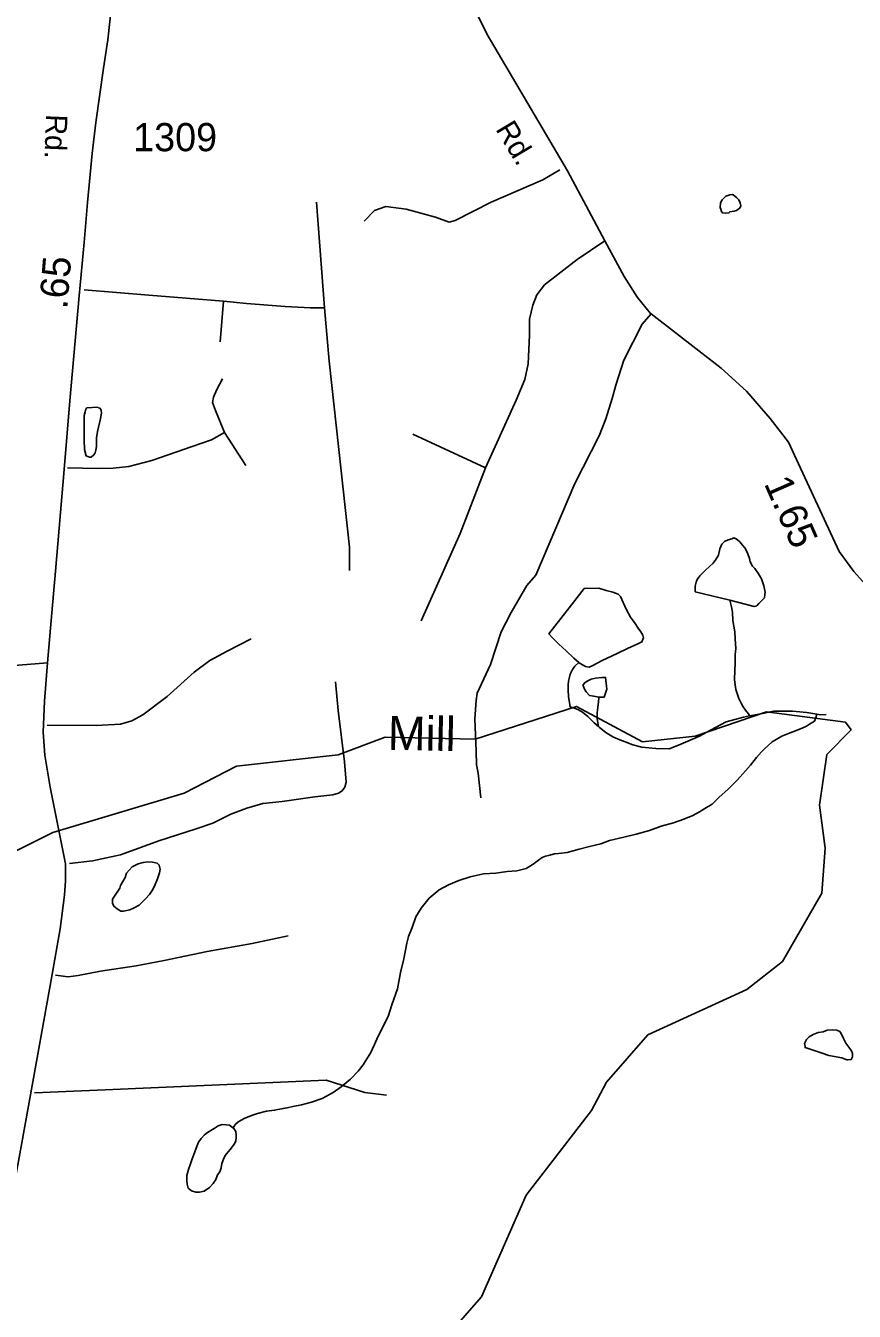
# Model space of a CAD drawing. Extents: x 2082433 to 2279600, y 546599 to 755198.
# Drawn here: x 2116350 to 2120022, y 621201 to 626902 of the extents above; entities that cross this region are included whole.
import ezdxf

# ---------------------------------------------------------------- set-up
doc = ezdxf.new("R2010")
doc.units = 0
for name, color, linetype in [('Exist Hydrographic Creek Single Shore', 7, 'Continuous'), ('Exist Hydrographic Creek Single Shore Label', 7, 'Continuous'), ('Exist Hydrographic Misc Water Feature', 7, 'Continuous'), ('Exist Road Non-System Type 51', 7, 'Continuous'), ('Exist Road Secondary Mileage Hundredths English Label', 7, 'Continuous'), ('Exist Road Secondary Type 51 Attributed', 7, 'Continuous'), ('Exist Road Secondary Type 51 Label', 7, 'Continuous'), ('Exist Road Secondary Type 51 Number Label', 7, 'Continuous')]:
    doc.layers.add(name, color=color, linetype=linetype)

msp = doc.modelspace()

# ---------------------------------------------------------------- linework, layer by layer
at = {"layer": 'Exist Hydrographic Creek Single Shore'}
for points in [[(2115933.5, 622147), (2115831.6, 622486.9), (2115839.6, 622696.8), (2115905.4, 622869.3), (2116162.6, 623172.4), (2116469.5, 623323.7), (2117052.5, 623498.9), (2117284.6, 623618.9), (2117734.5, 623668.8), (2117942.7, 623746.6), (2118342.5, 623738.5), (2118791.6, 623883.5), (2119083.6, 623726.7), (2119317.5, 623751.5), (2119633.7, 623860), (2119983.6, 623813.4), (2120008.6, 623780.1)], [(2117254.4, 619226.7), (2117410.5, 619676.3), (2117433.5, 620161.4), (2117506.5, 620461.7), (2117680.6, 620704.2), (2118129.6, 620990.4), (2118369.6, 621264.4), (2118567.6, 621716.3), (2118857.6, 622091), (2118923.6, 622217.6), (2119106.5, 622427.1), (2119546.6, 622628.1), (2119704.7, 622752.9), (2119878.6, 623054.5), (2119893.5, 623254.3), (2119868.7, 623445), (2119900.7, 623670.7), (2120008.6, 623780.1)]]:
    msp.add_lwpolyline(points, dxfattribs=at)
at = {"layer": 'Exist Hydrographic Misc Water Feature'}
for points in [[(2119470.6, 626076), (2119490.5, 626080.3), (2119500.6, 626082.4), (2119506.3, 626086.4), (2119514.5, 626092.4), (2119520, 626102.5), (2119516.3, 626116.5), (2119510.2, 626130.4), (2119500.4, 626140.4), (2119485.8, 626152.3), (2119481.9, 626154.2), (2119470.2, 626152.3), (2119452.2, 626146.1), (2119436.2, 626129.9), (2119430, 626116.2), (2119428.4, 626096.1), (2119430.4, 626088.1), (2119434.3, 626078.2), (2119438.4, 626071.9), (2119452.6, 626070.2), (2119466.5, 626072.1), (2119470.6, 626076)], [(2116620.8, 625207.9), (2116668.8, 625210.3), (2116672.7, 625208.1), (2116679.2, 625206.3), (2116684.8, 625196.2), (2116685.4, 625184.3), (2116679.2, 625152.4), (2116671.7, 625122.3), (2116667.4, 625102.3), (2116663.7, 625074.1), (2116663.7, 625048.5), (2116663.7, 625036.3), (2116660.2, 625020.2), (2116657.7, 625008.4), (2116651.8, 624998.3), (2116639.9, 624988), (2116631.9, 624988), (2116617.9, 624994.1), (2116609.9, 625022.1), (2116609.5, 625066), (2116609.5, 625113.8), (2116608.9, 625152), (2116609.3, 625173.9), (2116613.2, 625190), (2116616.9, 625202), (2116620.8, 625207.9)], [(2119470.2, 624354.4), (2119578.3, 624327.1), (2119590.2, 624329.4), (2119599.8, 624339.3), (2119623.8, 624365.2), (2119625.6, 624379.2), (2119627.7, 624389.4), (2119621.7, 624417.5), (2119611.5, 624449.5), (2119597.5, 624471), (2119581.1, 624495), (2119571.3, 624505), (2119561, 624525.2), (2119557.2, 624539.2), (2119546.9, 624567.1), (2119536.9, 624586.9), (2119526.6, 624599), (2119514.5, 624612.9), (2119504.7, 624622.6), (2119498.5, 624626.7), (2119488.7, 624630.7), (2119479, 624626.4), (2119463, 624622.4), (2119446.8, 624614.7), (2119434.9, 624602.3), (2119426.9, 624582.4), (2119421, 624554.5), (2119409.1, 624534.4), (2119397.2, 624518.4), (2119381.2, 624504.2), (2119361.5, 624486), (2119337.5, 624462.1), (2119325.6, 624446.1), (2119322, 624434), (2119317.7, 624416), (2119317.7, 624396.2), (2119317.4, 624392.2), (2119470.2, 624354.4)], [(2118801.3, 624077.7), (2118779.2, 624097.6), (2118744.9, 624129.6), (2118713, 624159.6), (2118684.9, 624187.4), (2118668.7, 624205.2), (2118748.2, 624307.5), (2118825.7, 624405.7), (2118889.9, 624408.1), (2118921.9, 624398), (2118952, 624390.3), (2118976, 624380.6), (2118986.1, 624370.5), (2119010.5, 624314.5), (2119030.4, 624278.7), (2119050.5, 624250.9), (2119064.8, 624230.8), (2119076.7, 624214.8), (2119084.7, 624199), (2119088.6, 624187.1), (2119081, 624169.2), (2119063, 624161), (2119017.3, 624140.7), (2118971.3, 624118.5), (2118905.3, 624086.3), (2118863.3, 624064.2), (2118847.5, 624058.1), (2118831.5, 624060.1), (2118807.1, 624074), (2118801.3, 624077.7)], [(2119470.2, 624354.4), (2119478, 624324.8), (2119482.5, 624300.7), (2119484.2, 624264.7), (2119492.4, 624214.8), (2119494.6, 624182.8), (2119497.1, 624140.7), (2119495, 624113), (2119495, 624072.8), (2119493, 624044.8), (2119491.5, 624000.8), (2119497.7, 623958.9), (2119509.8, 623918.9), (2119521.9, 623894.8), (2119530.3, 623881), (2119544, 623861.1), (2119554.3, 623849.3), (2119558, 623841.1)], [(2118801.3, 624077.7), (2118783.3, 624061.7), (2118773.4, 624047.8), (2118763.4, 624025.8), (2118757.9, 624007.6), (2118755.8, 623995.7), (2118753.6, 623979.8), (2118754.2, 623967.6), (2118754.2, 623957.5), (2118756, 623925.6), (2118762.2, 623883.6), (2118762, 623879.6)], [(2118890.1, 623924.3), (2118894, 623924.1), (2118908, 623924.4), (2118913.9, 623924.4), (2118925.8, 623960.3), (2118919.6, 624012.3), (2118903.4, 624012.3), (2118875.6, 624008), (2118855.9, 624004.1), (2118837.8, 623995.9), (2118827.6, 623988.1), (2118819.6, 623978), (2118821.6, 623972), (2118825.9, 623960), (2118834.1, 623947.8), (2118848.1, 623931.9), (2118867.8, 623928.1), (2118890.1, 623924.3)], [(2118890.1, 623924.3), (2118888.1, 623902.3), (2118884.2, 623868.5), (2118882.3, 623854.1), (2118882.5, 623828.1), (2118888.4, 623794), (2118892.6, 623790.5)], [(2118762, 623879.6), (2118766.3, 623879.8), (2118782.1, 623875.8), (2118800.3, 623867.7), (2118818.1, 623857.7), (2118840.5, 623838.2), (2118868.6, 623810.4), (2118888.4, 623794), (2118892.6, 623790.5)], [(2119558, 623841.1), (2119600.2, 623849.3), (2119666, 623861.6), (2119748.3, 623862.2), (2119812.2, 623856.1), (2119855.9, 623848.3)], [(2117266.7, 622015.7), (2117270.4, 622018), (2117280.9, 622031.8), (2117294.4, 622041.9), (2117318.6, 622056.1), (2117350.6, 622069.9), (2117376.6, 622078.1), (2117416.6, 622088.3), (2117452.5, 622092.6), (2117490.4, 622100.6), (2117508.3, 622102.8), (2117534.3, 622109), (2117572.2, 622117.1), (2117616.3, 622129), (2117664.1, 622145.3), (2117711.9, 622171.7), (2117748.2, 622195.9), (2117789.6, 622229.8), (2117823.6, 622266), (2117845.4, 622294.3), (2117861.2, 622320.3), (2117877.4, 622346.2), (2117895.2, 622384.5), (2117910.6, 622418.3), (2117956.7, 622508.6), (2117972.1, 622560.6), (2117997.9, 622631), (2118011.5, 622702.7), (2118025.2, 622764.7), (2118038.7, 622832.8), (2118046.7, 622862.8), (2118062.7, 622903), (2118078.5, 622950.9), (2118102.3, 622989.1), (2118138, 623033.2), (2118181.9, 623069.5), (2118223.9, 623091.6), (2118269.6, 623111.8), (2118319.7, 623128.2), (2118379.5, 623140.2), (2118433.3, 623144.6), (2118483.7, 623150.8), (2118527.2, 623154.7), (2118567.2, 623164.9), (2118599.2, 623183.2), (2118622.9, 623201.5), (2118638.9, 623213.3), (2118653.3, 623219.6), (2118667.2, 623221.6), (2118693.3, 623229.8), (2118710.9, 623231.6), (2118749, 623235.9), (2118802.8, 623250.1), (2118849.1, 623262.2), (2118898.7, 623274.5), (2118936.9, 623288.6), (2119000.8, 623302.9), (2119056.2, 623317.2), (2119114.2, 623333.6), (2119166.5, 623351.6), (2119220.3, 623367.8), (2119266.4, 623384), (2119306, 623400.3), (2119335.9, 623416.4), (2119360.1, 623430.6), (2119391.9, 623450.6), (2119422, 623478.8), (2119463.6, 623516.7), (2119503.4, 623556.9), (2119539.5, 623597.3), (2119562.9, 623623.4), (2119589.1, 623657.5), (2119610.5, 623681.4), (2119624.8, 623695.5), (2119658.7, 623725.7), (2119700.5, 623751.8), (2119730.4, 623763.9), (2119768.6, 623778), (2119794, 623788.3), (2119810.4, 623796.4), (2119824.3, 623804.4), (2119846.3, 623818.5), (2119852, 623832.7), (2119855.9, 623848.3)], [(2118892.6, 623790.5), (2118920.7, 623768.4), (2118952.7, 623748.5), (2118982.6, 623734.7), (2119006.8, 623727), (2119040.6, 623713), (2119081, 623703.2), (2119111.2, 623699.4), (2119143.2, 623697.4), (2119201, 623695.6), (2119242.8, 623711.9), (2119336.7, 623752.1), (2119384.5, 623778.5), (2119454.2, 623814.6), (2119531.9, 623835.3), (2119558, 623841.1)], [(2119855.9, 623848.3), (2119871.9, 623846.7), (2119897.7, 623846.9)], [(2116770.3, 623089.3), (2116789.8, 623125.3), (2116795.7, 623143.4), (2116808, 623157.4), (2116822.2, 623171.5), (2116847.4, 623185.5), (2116869.7, 623191.8), (2116891.7, 623193.8), (2116911.8, 623192), (2116931.7, 623187.8), (2116941.7, 623180.1), (2116946, 623162), (2116942.1, 623146.1), (2116933.9, 623118.1), (2116920.2, 623086.1), (2116910.3, 623067.7), (2116898.4, 623050), (2116880.6, 623029.6), (2116864.4, 623013.8), (2116852.5, 623001.8), (2116831, 622989.6), (2116810.5, 622981.4), (2116782.8, 622975.5), (2116770.7, 622975.2), (2116754.5, 622985.4), (2116740.8, 622997.2), (2116734.6, 623011.1), (2116734.2, 623029.1), (2116752.7, 623055.1), (2116766.2, 623077.4), (2116770.3, 623089.3)], [(2119880.5, 622345.2), (2119909, 622335.2), (2119966.4, 622325.3), (2119988.6, 622315.5), (2119992.9, 622315.6), (2120008.5, 622317.7), (2120014.8, 622329.8), (2120014.4, 622343.6), (2120010.5, 622355.6), (2119998.4, 622371.6), (2119984.3, 622389.6), (2119974.4, 622411.4), (2119964, 622433.6), (2119958, 622441.4), (2119944.3, 622447.5), (2119924.2, 622449.3), (2119902.1, 622447), (2119884, 622440.8), (2119862.1, 622436.8), (2119839.9, 622428.8), (2119822.1, 622418.6), (2119810.4, 622406.5), (2119802.2, 622388.7), (2119804.7, 622374.6), (2119804.4, 622370.5), (2119880.5, 622345.2)], [(2117266.7, 622015.7), (2117252.8, 622025.9), (2117238.4, 622027.6), (2117220.6, 622029.5), (2117202.5, 622023.3), (2117184.9, 622011.4), (2117155, 621993.3), (2117142.7, 621983.4), (2117126.9, 621967.1), (2117115.2, 621951), (2117104.9, 621925), (2117097.1, 621903.1), (2117087.5, 621876.9), (2117081.1, 621858.8), (2117071.5, 621829.1), (2117063.7, 621803.1), (2117064.1, 621779.1), (2117066, 621765), (2117069.7, 621747), (2117084, 621735.1), (2117103.7, 621729.2), (2117119.9, 621729.2), (2117140.2, 621733.1), (2117164, 621749.3), (2117180, 621767.6), (2117191.7, 621785.3), (2117199.9, 621805.6), (2117209.7, 621819.5), (2117215.5, 621837.7), (2117219.1, 621855.8), (2117227.1, 621875.7), (2117233.3, 621891.7), (2117247.4, 621907.5), (2117257.1, 621919.8), (2117273.1, 621941.7), (2117281.1, 621955.9), (2117282.7, 621971.9), (2117282.7, 621982), (2117280.7, 621997.7), (2117272.9, 622011.9), (2117266.7, 622015.7)]]:
    msp.add_lwpolyline(points, dxfattribs=at)
at = {"layer": 'Exist Road Non-System Type 51'}
for p, q in [((2117673.8, 625650.6), (2117638.7, 626120.2)), ((2117227.1, 625680.4), (2117211.9, 625500.5)), ((2117230.1, 625098), (2117324.7, 624951.6)), ((2118387.6, 624941.8), (2118065.7, 625091.2))]:
    msp.add_line(p, q, dxfattribs=at)
for points in [[(2118717.8, 626262.8), (2118642.1, 626218), (2118413, 626120), (2118253.2, 626038.5), (2118226.1, 626031), (2118165.8, 626053.6), (2118036.2, 626088.3), (2117945.7, 626100.3), (2117896, 626082.2), (2117849.3, 626035.5)], [(2118917.2, 625947.9), (2118794.6, 625864.9), (2118649.7, 625752.2), (2118615.2, 625708.6), (2118596.8, 625662.6), (2118583, 625600.5), (2118583, 625529.2), (2118576.1, 625402.8), (2118562.3, 625333.8), (2118523.3, 625241.8), (2118387.6, 624941.8)], [(2116608.1, 625730.7), (2116894.7, 625707.8), (2117227.1, 625680.4)], [(2117227.1, 625680.4), (2117327.7, 625669.7), (2117500, 625657.5), (2117611.3, 625650.6), (2117673.8, 625650.6)], [(2117673.8, 625650.6), (2117695.2, 625414.3), (2117727.2, 625117.8), (2117785.1, 624590.3), (2117785.1, 624486.6)], [(2119122.2, 625624.1), (2119081.9, 625578.1), (2119001.5, 625419.4), (2118964.7, 625307.9), (2118949.7, 625248.7), (2118921, 625158.5), (2118891.1, 625082.6), (2118783.1, 624872.3), (2118669.3, 624604.4), (2118610.6, 624465.9), (2118570.4, 624419.9), (2118501.4, 624300.3), (2118456.6, 624213.6), (2118409.4, 624069.9), (2118350.8, 623942.8), (2118346.2, 623909.5), (2118340.5, 623827.9), (2118346.2, 623684.8), (2118347.4, 623625), (2118355.4, 623587), (2118366.9, 623478.4)], [(2117230.1, 625098), (2117190.5, 625195.5), (2117178.3, 625230.6), (2117181.4, 625255), (2117196.6, 625288.5), (2117222.5, 625335.8)], [(2116534.9, 624941.7), (2116667.6, 624938.6), (2116737.7, 624940.2), (2116806.3, 624947.8), (2116908.4, 624973.7), (2117086.8, 625036.2), (2117173.7, 625065.2), (2117230.1, 625098)], [(2118387.6, 624941.8), (2118275, 624649.8), (2118102.5, 624262.4)], [(2116444.8, 623800.3), (2116662.1, 623799.1), (2116770.2, 623804.9), (2116820.8, 623819.8), (2116869, 623846.3), (2116977.1, 623926.7), (2117096.6, 624035.4), (2117165.6, 624087.1), (2117242.6, 624128.5), (2117348.4, 624183.7)], [(2116543.7, 623186.4), (2116646, 623198.5), (2116770.2, 623224.9), (2116940.3, 623287), (2117104.7, 623341), (2117179.4, 623366.3), (2117258.7, 623405.4), (2117330, 623431.9), (2117401.3, 623452.5), (2117486.4, 623462.3), (2117631.2, 623481.9), (2117710.5, 623491.6), (2117735.8, 623498.5), (2117753, 623508.9), (2117764.5, 623525), (2117770.3, 623546.8), (2117763.4, 623637.6), (2117734.7, 623864.7), (2117723.2, 623991.7)], [(2116481.6, 622692.1), (2116538, 622684.6), (2116582.8, 622690.4), (2116681.7, 622709.9), (2116839.1, 622732.9), (2116963.3, 622757.1), (2117154.1, 622796.1), (2117353, 622832.4), (2117512.8, 622865.7)], [(2116388.5, 622169.1), (2116701.5, 622183.2), (2117681.2, 622225.4), (2117853, 622171.1), (2117949.5, 622159.1)]]:
    msp.add_lwpolyline(points, dxfattribs=at)
at = {"layer": 'Exist Road Secondary Type 51 Attributed'}
for points in [[(2116707.7, 627475.4), (2116724.5, 627267.7), (2116735.2, 627083.8), (2116730.6, 626988.6), (2116713.4, 626839.2), (2116694.5, 626713.6), (2116660.5, 626473), (2116644.9, 626335.1), (2116624.3, 626118.4), (2116608.7, 625940.2), (2116587.2, 625704.4), (2116545.3, 625238.9), (2116520.7, 624933.5), (2116481.7, 624482.8), (2116466.1, 624298.9), (2116446.8, 624076.4)], [(2120097.8, 624395.4), (2120020.3, 624482.2), (2119955.9, 624569.8), (2119774.7, 624959.1), (2119730, 625055.3), (2119649.4, 625160.5), (2119544.7, 625280.9), (2119431.6, 625383.9), (2119122.2, 625624.1), (2119118.6, 625626.4), (2119061.3, 625696.1), (2119002.4, 625789.9), (2118917.2, 625947.9), (2118751.4, 626257.8), (2118395.7, 626863.6), (2118331.5, 626992.2)], [(2116446.8, 624076.4), (2116187.1, 624056), (2115831.1, 624014), (2115576.7, 623962.5), (2115366.6, 623892.4), (2115162.6, 623823.4)], [(2116446.8, 624076.4), (2116433.6, 623907.3), (2116427.1, 623769.4), (2116434.9, 623666.8), (2116457.9, 623525.6), (2116500.1, 623318.7), (2116525.6, 623184.8), (2116526.4, 623110.1), (2116521.5, 623046.1), (2116501.8, 622897.5), (2116465.7, 622687.3), (2116397.1, 622308.9), (2116329.8, 621931.2), (2116261.2, 621559.3), (2116219.4, 621330.3), (2116178.3, 621104.5)]]:
    msp.add_lwpolyline(points, dxfattribs=at)

# ---------------------------------------------------------------- texts
at = {"layer": 'Exist Hydrographic Creek Single Shore Label'}
msp.add_text('Mill', height=150, rotation=358.8108, dxfattribs=at).set_placement((2117953.5, 623691.2))
at = {"layer": 'Exist Road Secondary Mileage Hundredths English Label'}
for s, rotation, p in [('.65', 85.4414, (2116533.4, 625642.9)), ('1.65', 293.6421, (2119620.6, 624872.2))]:
    msp.add_text(s, height=125, rotation=rotation, dxfattribs=at).set_placement(p)
at = {"layer": 'Exist Road Secondary Type 51 Label'}
for rotation, p in [(267.7639, (2116440.3, 626510.6)), (300.9756, (2118430.1, 626443.5))]:
    msp.add_text('Rd.', height=95, rotation=rotation, dxfattribs=at).set_placement(p)
at = {"layer": 'Exist Road Secondary Type 51 Number Label'}
msp.add_text('1309', height=125, dxfattribs=at).set_placement((2116826, 626345.4))

doc.saveas('drawing.dxf')
